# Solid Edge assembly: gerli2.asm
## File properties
Author: priit
Template: Normal.asm
Last saved by: Anon
Revision: 4
Application: Solid Edge
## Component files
gerlilaev1.par
gerlikatus.par
gerlimetal.psm
lg.par
lg_mir3.par
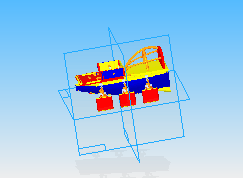
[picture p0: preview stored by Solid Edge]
